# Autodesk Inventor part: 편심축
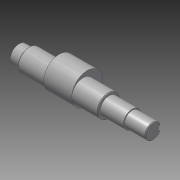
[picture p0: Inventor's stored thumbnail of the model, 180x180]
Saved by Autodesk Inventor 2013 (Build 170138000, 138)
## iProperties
Created: 2015-10
Part Number: 편심축
Document SubType Name: Modeling
Designer: mdu
Density: 7.86 g/cm^3
Material: 강철, 연강
Mass: 1216.6 g
Surface Area: 217.48 cm^2
Volume: 154.784 cm^3
Author: mdu
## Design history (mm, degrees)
sketch "스케치1"
  geometry: L1 (-20.5, -41.331)-(-20.5, 32.669) reference; L2 (7.5, -30.031)-(7.5, 21.369) reference; L3 (135.5, -30.331)-(135.5, 21.669) reference; L4 (121.5, 21.369)-(121.5, -30.031) reference; L5 (184.5, -4.331)-(-7.5, -4.331); L6 (184.5, -4.331)-(184.5, 6.669); L7 (154.5, 8.169)-(121.5, 8.169); L8 (121.5, 8.169)-(121.5, 11.669); L9 (121.5, 11.669)-(7.5, 11.669); L10 (7.5, 11.669)-(7.5, 8.169); L11 (7.5, 8.169)-(-7.5, 8.169); L12 (-7.5, 8.169)-(-7.5, -4.331); L13 (154.5, 8.169)-(154.5, 6.669); L14 (154.5, 6.669)-(184.5, 6.669); C1 r 32.5 at (64.5, -4.331) reference; 1 further point
  constraints: 21 end point, 8 perpendicular, 5 point on line, 1 collinear
  dimensions: "d1" = 25 diameter of L11 L5; "d2" = 32 diameter of L9 L5; "d4" = 15 distance of L10.end L11.end; "d15" = 33 distance of L7.start L7.end; "d26" = 30 distance of L13.end L6.end; "d36" = 22 diameter of L14 L5
revolve "회전1" sketch "스케치1" stored, may be unused: angle "d6" = 90 deg
node "작업 평면1"
sketch "스케치2"
  geometry: C1 r 16 at (0, 0) reference; C2 r 22 at (0, 6)
  constraints: 1 centre point, 1 vertical alignment
  dimensions: "d34" = 6 distance of C2.centre C1.centre; "d35" = 44 diameter of C2
extrude "돌출1" join sketch "스케치2" stored distance "d9" = 40; taper "d10" = 0 deg
chamfer "모따기1" distance "d11" = 1; stored, may be unused: second distance "d12" = 2, angle "d13" = 45 deg
node "작업 평면2"
sketch "스케치3"
  geometry: L1 (-15, -10)-(-15, 10) reference; L2 (-15, 3)-(0, 3); L3 (0, -3)-(-15, -3); A1 r 3 centre (0, 0) between (0, -3) and (0, 3); 2 further points
  constraints: 4 end point, 2 perpendicular, 2 point on circle, 2 point on line, 2 tangent, 1 centre point, 1 horizontal alignment, 1 midpoint
  dimensions: "d16" = 18 dimension on A1 L1; "d17" = 6 distance between parallel lines of L3 L2
extrude "돌출2" cut sketch "스케치3" distance "d18" = 3.5; taper "d19" = 0 deg
node "솔리드1"
node "참조1"
node "참조2"
node "참조3"
node "참조4"
node "참조5"
other parameters: "d30" = 35
